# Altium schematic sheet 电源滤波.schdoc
size 297 x 209 mm; Symbol: Drawing-Symbol_A4; Company: 嘉立创EDA; Version: V1.0; Page Size: A4; @Project Name: 水墨屏demo1; @Page Count: 2; @Update Date: 2026-02-28; @Create Date: 2026-02-28; @Schematic Name: stm32F407最小系统; @Page No: 2; @Page Name: P2; Device: Drawing-Symbol_A4; @Board Name: 2_STM32F407最小系统; @Create Time: 14:40:09; @Update Time: 14:40:09; @Assembly Variant: Basic; Border: 1; Title Block Position: 3; Size: A4; Width: 1170; Height: 825; Region Start: 1; X Region Count: 6; Y Region Count: 4; Blade Width: 10
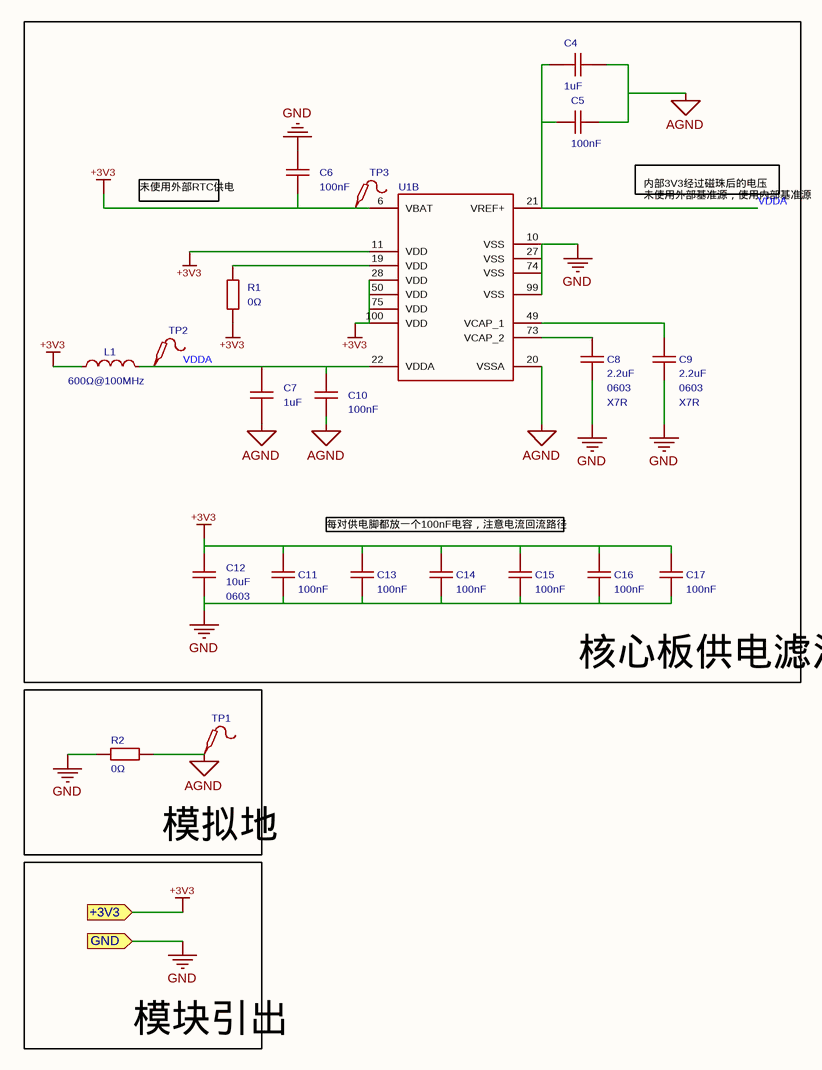
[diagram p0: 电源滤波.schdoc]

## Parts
C4  1uF  [C0603]
C5  100nF  [C0603]
C6  100nF  [C0603]
C7  1uF  [C0603]
C8  Supplier Footprint: 0603  Temperature Coefficient: X7R  [C0603]  (hidden comment: 2.2uF)
C9  Supplier Footprint: 0603  Temperature Coefficient: X7R  [C0603]  (hidden comment: 2.2uF)
C10  100nF  [C0603]
C11  100nF  [C0603]
C12  Supplier Footprint: 0603  [C0603]  (hidden comment: 10uF)
C13  100nF  [C0603]
C14  100nF  [C0603]
C15  100nF  [C0603]
C16  100nF  [C0603]
C17  100nF  [C0603]
L1  Impedance @ Frequency: 600Ω@100MHz  [L0603]  (hidden comment: GZ1608D601TF)
R1  0Ω  [R0603]
R2  0Ω  [R0603]
TP1  (no value)  [Test-Point-1.27mm]
TP2  (no value)  [Test-Point-1.27mm]
TP3  (no value)  [Test-Point-1.27mm]
U1  (no value)  [LQFP-100_L14.0-W14.0-P0.50-LS16.0-BL]  (part B of 2)

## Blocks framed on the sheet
核心板供电滤波: C4-C17 L1 R1 TP2 TP3 U1
模拟地: R2 TP1

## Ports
+3V3 (in), GND (in)

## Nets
+3V3: C6.1 C11.2 C12.2 C13.2 C14.2 C15.2 C16.2 C17.2 L1.1 R1.1 TP3.1 U1.6(VBAT) U1.11(VDD) U1.28(VDD) U1.50(VDD) U1.75(VDD) U1.100(VDD) ; port +3V3
AGND: C4.1 C5.2 C7.2 C10.1 R2.2 TP1.1 U1.20(VSSA)
GND: C6.2 C8.1 C9.1 C11.1 C12.1 C13.1 C14.1 C15.1 C16.1 C17.1 R2.1 U1.10(VSS) U1.27(VSS) U1.74(VSS) U1.99(VSS) ; port GND
VDDA: C4.2 C5.1 C7.1 C10.2 L1.2 TP2.1 U1.21(VREF+) U1.22(VDDA)
NetC8_2: C8.2 U1.73(VCAP_2)
NetC9_2: C9.2 U1.49(VCAP_1)
NetR1_2: R1.2 U1.19(VDD)

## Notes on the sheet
- 未使用外部RTC供电
- (near C9) 内部3V3经过磁珠后的电压
  未使用外部基准源，使用内部基准源
- 每对供电脚都放一个100nF电容，注意电流回流路径
- 模块引出

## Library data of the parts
C4 C7 = CL10B105KP8NNNC: 容值:1uF;精度:±10%;额定电压:10V;温度系数:X7R;; Manufacturer: SAMSUNG(三星); AddInBom: yes; ModelId: ac125912035d415993ca9572d50418b10819f05c4eef4c71ace90d822a990e87; ModelName: C0603_L1.6-W0.8-H0.8; ModelTransform: 62.992,31.496,0,0,0,0,0,0,0; Tolerance: ±10%; Voltage Rating: 10V; Temperature Coefficient: X7R
C5 C6 C10 C11 C13-C17 = CL10B104KO8NNNC: 容值:100nF;精度:±10%;额定电压:16V;温度系数:X7R;; Manufacturer: SAMSUNG(三星); AddInBom: yes; ModelId: ac125912035d415993ca9572d50418b10819f05c4eef4c71ace90d822a990e87; ModelName: C0603_L1.6-W0.8-H0.8; ModelTransform: 62.992,31.496,0,0,0,0,0,0,0; Tolerance: ±10%; Voltage Rating: 16V; Temperature Coefficient: X7R
C8 C9 = 0603B225K160NT: 温度系数:X7R;容值:2.2uF;精度:±10%;额定电压:16V;; Manufacturer: FH(风华); 3D Model: ac125912035d415993ca9572d50418b1; 3D Model Transform: 62.992,31.496,0,0,0,0,0,0,0; Tolerance: ±10%; Voltage Rated: 16V; AddInBom: yes; ModelName: C0603_L1.6-W0.8-H0.8
C12 = 0603X106K100NT: 容值:10uF;精度:±10%;额定电压:10V;材质(温度系数):X5R;; Manufacturer: FH(风华); 3D Model: ac125912035d415993ca9572d50418b1; 3D Model Transform: 62.992,31.496,0,0,0,0,0,0,0; Tolerance: ±10%; Voltage Rated: 10V; Temperature Coefficient: X5R; AddInBom: yes; ModelName: C0603_L1.6-W0.8-H0.8
L1 = GZ1608D601TF: 标称阻抗@测试频率:600Ω@100MHz;误差:±25%;直流电阻(RDC):450mΩ;; Manufacturer: Sunlord(顺络); 3D Model: 2bc5ec593d464d6ba9807aec0b5673c2; 3D Model Transform: 62.992,31.496,0,180,0,0,0.094,0.629,0; Tolerance: ±25%; DC Resistance: 450mΩ; Current Rating: 200mA; Circuits: 1; AddInBom: yes; ModelName: L0603_L1.6-W0.8-H0.5_BEAD
R1 R2 = RC0603FR-070RL: 电阻类型:厚膜电阻;阻值:0Ω;精度:±1%;功率:100mW;工作电压:75V;温度系数:-;; Manufacturer: YAGEO(国巨); AddInBom: yes; ModelId: fc143cca1e79419f9cd78b61e9279f080819f05c4eef4c71ace90d822a990e87; ModelTransform: 31.8897,63.7794,0,90,0,0,0,0,0; Tolerance: ±1%; Power(Watts): 100mW; Voltage-Supply(Max): 75V
TP1-TP3 = Test-Point: Test Point 测试点; AddInBom: yes
U1 = STM32F407VET6【自修改】: CPU内核:ARM Cortex-M4;CPU最大主频:168MHz;工作电压范围:1.8V~3.6V;内部振荡器:有;程序 FLASH容量:512K@x8bit;RAM总容量:192KB;EEPROM/数据 FLASH容量:-;GPIO端口数量:82;ADC(单元数/通道数/位数):1@x16ch/12bit;DAC(单元数/通道数/位数):1@x2ch/12bit;外设/功能/协议栈:欠压检测/复位；DMA；LCD驱动；看门狗；POR；PWM;工作温度范围:-40℃~+85℃;; Manufacturer: ST(意法半导体); Relevance: []; Maximum Frequency: 168MHz; Internal Oscillator: 有; RAM Size: 192KB; GPIO Ports Number: 82; 3D Model: 469e6cc70557486dbd01fd12ff814964; 3D Model Transform: 629.92,629.92,0,0,0,0,0,0,0; AddInBom: yes; ModelName: LQFP-100_L14.0-W14.0-H1.4-LS16.0-P0.50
